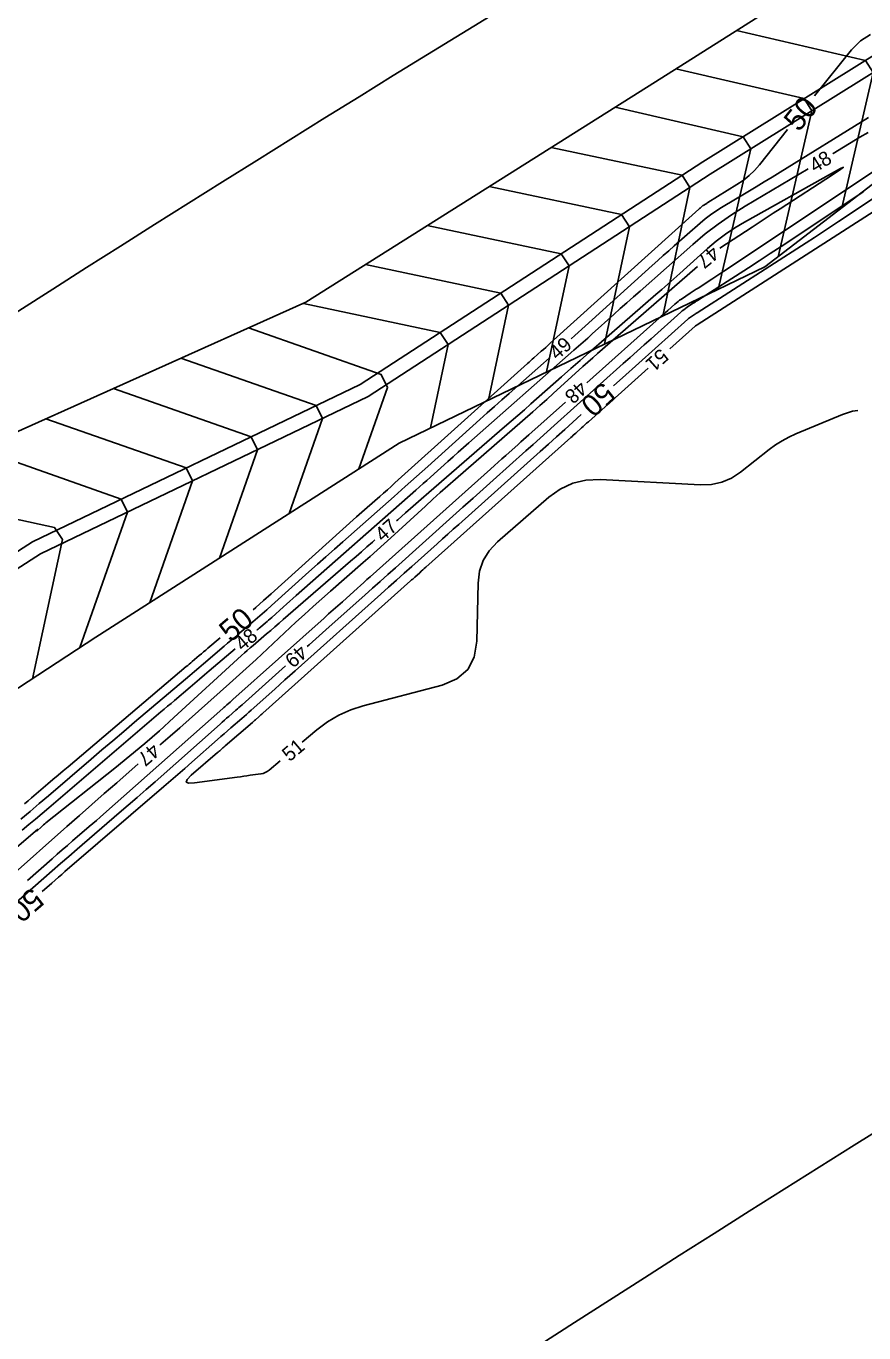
# Model space of a CAD drawing. Extents: x 2384780 to 2405861, y 547869 to 573706.
# Drawn here: x 2392685.5 to 2392801.8, y 553648.5 to 553830.1 of the extents above; entities that cross this region are included whole.
import ezdxf

# ---------------------------------------------------------------- set-up
doc = ezdxf.new("R2010")
doc.units = 0
for name, color, linetype in [('Old_Level_5', 7, 'Continuous'), ('Old_Level_60', 7, 'Continuous'), ('Old_Level_61', 7, 'Continuous'), ('Old_Level_63', 7, 'Continuous'), ('Sheet Plan CELL', 7, 'Continuous')]:
    doc.layers.add(name, color=color, linetype=linetype)

msp = doc.modelspace()

# ---------------------------------------------------------------- linework, layer by layer
at = {"layer": 'Old_Level_5'}
msp.add_arc((2394828.31077, 550434.91596), 3822, 118.42377222, 123.93929722, dxfattribs=at)
at = {"layer": 'Old_Level_60'}
for points in [[(2392802.48475, 553817.3955), (2392790.23975, 553809.82325), (2392789.12175, 553809.13525), (2392788.001, 553808.4515), (2392786.8775, 553807.7725), (2392785.75125, 553807.098), (2392782.0675, 553804.90225), (2392781.29075, 553804.4145), (2392780.539, 553803.89225), (2392779.8125, 553803.33575), (2392779.111, 553802.745), (2392775.52025, 553799.576), (2392774.75175, 553798.89575), (2392773.98525, 553798.2135), (2392773.22075, 553797.529), (2392772.458, 553796.8425), (2392763.14475, 553788.43475), (2392761.701, 553787.13525), (2392761.1815, 553786.6705)], [(2392802.436, 553815.3085), (2392801.27975, 553814.675), (2392797.57975, 553812.387), (2392797.51625, 553812.348)], [(2392794.0955, 553810.27475), (2392785.356, 553805.065), (2392783.45025, 553803.86875), (2392781.60625, 553802.58775), (2392779.82375, 553801.22275), (2392778.10275, 553799.773), (2392770.761, 553793.2935), (2392769.84275, 553792.48075), (2392768.927, 553791.6655), (2392768.01325, 553790.84775), (2392767.102, 553790.0275), (2392764.129, 553787.3435), (2392763.491, 553786.76925), (2392762.8515, 553786.197), (2392762.21, 553785.6265), (2392761.567, 553785.058), (2392746.98375, 553772.20225), (2392746.24925, 553771.553), (2392745.51675, 553770.90175), (2392744.78575, 553770.24825), (2392744.05675, 553769.593), (2392741.67825, 553767.449), (2392741.16775, 553766.99025), (2392740.656, 553766.533), (2392740.143, 553766.07725), (2392739.62875, 553765.623), (2392722.99925, 553750.98), (2392722.556, 553750.5885), (2392722.114, 553750.196), (2392721.67275, 553749.80225), (2392721.23275, 553749.4075), (2392719.60525, 553747.9425), (2392719.393, 553747.75275), (2392719.17925, 553747.56475), (2392718.96425, 553747.3785), (2392718.74775, 553747.1935), (2392718.03825, 553746.59275), (2392717.88625, 553746.46375), (2392717.7345, 553746.33475), (2392717.58275, 553746.2055), (2392717.57375, 553746.19775)], [(2392781.85, 553799.24825), (2392786.31325, 553802.17875), (2392787.2885, 553802.818), (2392788.26475, 553803.456), (2392789.24175, 553804.09225), (2392790.21975, 553804.72725), (2392797.4895, 553809.4395), (2392798.65, 553810.20975), (2392799.016, 553810.50075), (2392798.58775, 553810.31275), (2392797.365, 553809.64575), (2392785.275, 553802.8785), (2392783.9165, 553802.068), (2392782.6095, 553801.186), (2392781.3535, 553800.23225), (2392780.149, 553799.20675), (2392776.298, 553795.74025), (2392775.471, 553794.99925), (2392774.6405, 553794.2625), (2392773.8065, 553793.52975), (2392772.96875, 553792.801), (2392765.03825, 553785.93525), (2392763.731, 553784.79975), (2392762.42725, 553783.66025), (2392761.127, 553782.51675), (2392759.83025, 553781.369), (2392755.6005, 553777.61325), (2392754.69275, 553776.81), (2392753.78275, 553776.00925), (2392752.8705, 553775.21125), (2392751.9555, 553774.416), (2392741.4385, 553765.301), (2392740.3535, 553764.3585), (2392739.27075, 553763.41375), (2392738.19, 553762.46625), (2392737.1115, 553761.51675), (2392736.93925, 553761.36475)], [(2392763.36875, 553780.5345), (2392773.3985, 553789.51475), (2392773.70125, 553789.786), (2392774.00425, 553790.057), (2392774.307, 553790.32825), (2392774.61, 553790.5995), (2392775.59925, 553791.4855), (2392775.8145, 553791.67125), (2392776.03575, 553791.84925), (2392776.26325, 553792.019), (2392776.49675, 553792.181), (2392777.7415, 553793.01125), (2392778.00875, 553793.18875), (2392778.2765, 553793.36475), (2392778.54525, 553793.53975), (2392778.8145, 553793.71375), (2392780.74975, 553794.9565), (2392781.164, 553795.22375), (2392781.577, 553795.49275), (2392781.98875, 553795.7635), (2392782.3995, 553796.036), (2392803.18575, 553809.8895)], [(2392724.52275, 553743.886), (2392724.79125, 553744.1265), (2392726.18775, 553745.377), (2392727.58425, 553746.62775), (2392732.5345, 553751.06075), (2392733.59525, 553752.0105), (2392734.656, 553752.9605), (2392735.71675, 553753.91025), (2392736.7775, 553754.86025), (2392744.77475, 553762.0205), (2392746.1705, 553763.27025), (2392747.56625, 553764.52), (2392748.96225, 553765.77), (2392750.358, 553767.02), (2392754.91725, 553771.103), (2392755.89425, 553771.978), (2392756.8715, 553772.85275), (2392757.8485, 553773.72775), (2392758.8255, 553774.6025), (2392768.4325, 553783.20425), (2392769.401, 553784.07125), (2392770.3695, 553784.9385), (2392771.338, 553785.80575), (2392772.3065, 553786.67325), (2392776.405, 553790.3435), (2392776.6185, 553790.528), (2392776.8385, 553790.70475), (2392777.0645, 553790.8735), (2392777.2965, 553791.03425), (2392778.06475, 553791.54675), (2392778.22975, 553791.65625), (2392778.395, 553791.765), (2392778.56075, 553791.873), (2392778.727, 553791.98025), (2392785.80525, 553796.52625), (2392787.31975, 553797.5035), (2392788.83025, 553798.48725), (2392790.3365, 553799.4775), (2392791.83875, 553800.474), (2392801.73375, 553807.06875)], [(2392803.282, 553804.3965), (2392778.693, 553788.604), (2392778.6625, 553788.5845), (2392778.63225, 553788.56475), (2392778.602, 553788.545), (2392778.572, 553788.525), (2392778.47375, 553788.4595), (2392778.453, 553788.445), (2392778.43275, 553788.43), (2392778.41325, 553788.41425), (2392778.394, 553788.39775), (2392774.88925, 553785.25875)], [(2392704.08525, 553730.21675), (2392704.2055, 553730.32125), (2392705.5175, 553731.46575), (2392706.8265, 553732.61375), (2392708.13225, 553733.76525), (2392709.43525, 553734.92025), (2392713.76475, 553738.7685), (2392714.69, 553739.596), (2392715.6105, 553740.4285), (2392716.526, 553741.2665), (2392717.43675, 553742.11), (2392722.97425, 553747.2685), (2392724.16525, 553748.36925), (2392725.36475, 553749.4605), (2392726.5725, 553750.54225), (2392727.789, 553751.61475), (2392732.3195, 553755.57775), (2392733.28775, 553756.43), (2392734.25075, 553757.288), (2392735.2085, 553758.15175), (2392736.16075, 553759.0215), (2392740.95525, 553763.42675), (2392741.9855, 553764.3675), (2392743.02175, 553765.3015), (2392744.06375, 553766.229), (2392745.112, 553767.14975), (2392755.859, 553776.53125), (2392756.8295, 553777.3825), (2392757.79575, 553778.2385), (2392758.75775, 553779.0995), (2392759.7155, 553779.965), (2392762.8375, 553782.80025), (2392763.508, 553783.406), (2392764.1815, 553784.0085), (2392764.85825, 553784.6075), (2392765.53775, 553785.203), (2392778.75425, 553796.72475)], [(2392758.1935, 553784.011), (2392757.34675, 553783.2625), (2392752.587, 553779.0665), (2392751.56825, 553778.166), (2392750.552, 553777.2625), (2392749.53825, 553776.35625), (2392748.527, 553775.4475), (2392741.27425, 553768.9095), (2392739.718, 553767.511), (2392738.15775, 553766.11675), (2392736.59325, 553764.72725), (2392735.025, 553763.342), (2392729.4925, 553758.4705), (2392728.30825, 553757.42475), (2392727.127, 553756.376), (2392725.9485, 553755.32425), (2392724.773, 553754.269), (2392719.5715, 553749.587), (2392718.932, 553749.016), (2392718.2885, 553748.44975), (2392717.64075, 553747.88825), (2392716.9885, 553747.33175), (2392714.8515, 553745.5215), (2392714.39375, 553745.13325), (2392713.9365, 553744.74475), (2392713.47975, 553744.3555), (2392713.02325, 553743.96575), (2392710.1235, 553741.48625), (2392709.502, 553740.9555), (2392708.87975, 553740.42525), (2392708.25675, 553739.89575), (2392707.63325, 553739.367), (2392700.568, 553733.382), (2392699.05475, 553732.09875), (2392697.54275, 553730.814), (2392696.03225, 553729.52775), (2392694.52275, 553728.23975), (2392688.5895, 553723.171), (2392687.3175, 553722.0855), (2392686.04425, 553721.00125), (2392684.77, 553719.9185)], [(2392771.90925, 553782.59025), (2392763.58525, 553775.136), (2392763.34275, 553774.91875), (2392763.10025, 553774.7015), (2392762.85775, 553774.48425), (2392762.615, 553774.26725), (2392761.82275, 553773.55775), (2392761.653, 553773.40575), (2392761.48325, 553773.25375), (2392761.3135, 553773.10175), (2392761.1435, 553772.9495), (2392741.0095, 553754.91875), (2392740.79875, 553754.73025), (2392740.588, 553754.5415), (2392740.3775, 553754.353), (2392740.16675, 553754.16425), (2392739.47875, 553753.54825), (2392739.33125, 553753.41625), (2392739.18375, 553753.284), (2392739.03625, 553753.152), (2392738.889, 553753.02), (2392718.37075, 553734.64525), (2392718.2285, 553734.51775), (2392718.08625, 553734.3905), (2392717.944, 553734.263), (2392717.80175, 553734.13575), (2392717.337, 553733.71975), (2392717.23725, 553733.63075), (2392717.137, 553733.54225), (2392717.0365, 553733.45425), (2392716.9355, 553733.36675), (2392713.1645, 553730.115), (2392713.0565, 553730.0215), (2392712.9485, 553729.9275), (2392712.841, 553729.833), (2392712.734, 553729.7385), (2392712.38425, 553729.42825), (2392712.30925, 553729.362), (2392712.234, 553729.296), (2392712.15825, 553729.23025), (2392712.0825, 553729.165), (2392708.414, 553726.01325), (2392707.8545, 553725.44), (2392707.748, 553725.07075), (2392708.095, 553724.906), (2392708.895, 553724.94525), (2392714.8045, 553725.75925), (2392715.26025, 553725.822), (2392715.71575, 553725.88475), (2392716.1715, 553725.9475), (2392716.627, 553726.01025), (2392718.1155, 553726.21525), (2392718.4255, 553726.2795), (2392718.717, 553726.385), (2392718.99025, 553726.5315), (2392719.24525, 553726.71875), (2392720.78975, 553728.0245)], [(2392685.69375, 553711.38), (2392689.11175, 553714.413), (2392689.81675, 553715.036), (2392690.524, 553715.65625), (2392691.234, 553716.2735), (2392691.94625, 553716.888), (2392694.27725, 553718.8905), (2392694.77575, 553719.3205), (2392695.27275, 553719.7525), (2392695.768, 553720.1865), (2392696.2615, 553720.6225), (2392712.79875, 553735.2885), (2392712.939, 553735.4125), (2392713.07975, 553735.536), (2392713.22075, 553735.659), (2392713.3625, 553735.7815), (2392713.8255, 553736.181), (2392713.92475, 553736.26675), (2392714.02325, 553736.353), (2392714.1215, 553736.43975), (2392714.2195, 553736.527), (2392726.8695, 553747.85325), (2392727.50675, 553748.424), (2392728.144, 553748.9945), (2392728.78125, 553749.56525), (2392729.41825, 553750.13575), (2392731.49975, 553751.99975), (2392731.946, 553752.39925), (2392732.392, 553752.79875), (2392732.838, 553753.198), (2392733.284, 553753.5975), (2392750.0025, 553768.5665), (2392750.529, 553769.038), (2392751.0555, 553769.50925), (2392751.582, 553769.98075), (2392752.1085, 553770.45225), (2392753.82825, 553771.9925), (2392754.197, 553772.3225), (2392754.5655, 553772.6525), (2392754.934, 553772.9825), (2392755.3025, 553773.3125), (2392760.38875, 553777.8665)], [(2392723.8445, 553730.607), (2392725.8825, 553732.33025), (2392727.35225, 553733.4415), (2392728.91675, 553734.37025), (2392730.576, 553735.11675), (2392732.33, 553735.68075), (2392743.277, 553738.554), (2392745.33675, 553739.396), (2392746.82375, 553740.69), (2392747.73825, 553742.43625), (2392748.08, 553744.63475), (2392748.2655, 553752.70225), (2392748.46325, 553754.35675), (2392748.9775, 553755.86275), (2392749.808, 553757.22), (2392750.955, 553758.42875), (2392758.09675, 553764.637), (2392759.689, 553765.78825), (2392761.405, 553766.581), (2392763.2445, 553767.01575), (2392765.20775, 553767.092), (2392779.17425, 553766.38275), (2392780.68375, 553766.434), (2392782.11075, 553766.745), (2392783.455, 553767.31575), (2392784.7165, 553768.1465), (2392788.7025, 553771.2845), (2392789.57525, 553771.92475), (2392790.48575, 553772.501), (2392791.434, 553773.01275), (2392792.4195, 553773.4605), (2392798.871, 553776.12975), (2392800.26325, 553776.59075), (2392801.024, 553776.71925)], [(2392733.94025, 553758.718), (2392733.5915, 553758.41025), (2392732.8365, 553757.7455), (2392732.08025, 553757.08225), (2392731.32225, 553756.42075), (2392730.563, 553755.761), (2392721.1945, 553747.6365), (2392720.622, 553747.141), (2392720.04875, 553746.6465), (2392719.4745, 553746.15325), (2392718.8995, 553745.66075), (2392717.01925, 553744.054), (2392716.618, 553743.70775), (2392716.2195, 553743.35825), (2392715.82425, 553743.0055), (2392715.43225, 553742.649), (2392706.0225, 553734.022), (2392704.014, 553732.2125), (2392701.9745, 553730.439), (2392699.9045, 553728.7015), (2392697.8035, 553727), (2392688.245, 553719.3965), (2392688.08775, 553719.26875), (2392687.93325, 553719.13725), (2392687.7815, 553719.00275), (2392687.6325, 553718.865), (2392687.021, 553718.28625), (2392686.99125, 553718.26025), (2392686.97775, 553718.2545), (2392686.981, 553718.26875), (2392687.00075, 553718.303), (2392687.092, 553718.44825), (2392687.10575, 553718.4725), (2392687.1075, 553718.483), (2392687.09725, 553718.47975), (2392687.07525, 553718.46275), (2392665.36675, 553699.9315)], [(2392714.5335, 553743.5985), (2392710.929, 553740.5165), (2392710.26425, 553739.949), (2392709.599, 553739.382), (2392708.933, 553738.81575), (2392708.26625, 553738.2505), (2392706.0875, 553736.40475), (2392705.62075, 553736.00925), (2392705.1545, 553735.613), (2392704.68875, 553735.21625), (2392704.22325, 553734.819), (2392688.63775, 553721.505), (2392687.71925, 553720.72125), (2392686.80025, 553719.9385), (2392685.88025, 553719.15675), (2392684.9595, 553718.37575)], [(2392682.6115, 553706.9785), (2392687.95725, 553711.722), (2392689.10475, 553712.73625), (2392690.25625, 553713.74575), (2392691.412, 553714.75075), (2392692.5715, 553715.751), (2392698.42175, 553720.777), (2392699.67325, 553721.8565), (2392700.9205, 553722.94075), (2392702.16325, 553724.03), (2392703.402, 553725.12425), (2392712.4345, 553733.13475), (2392712.73525, 553733.4005), (2392713.037, 553733.66525), (2392713.33975, 553733.929), (2392713.64325, 553734.19175), (2392714.6365, 553735.04825), (2392714.84875, 553735.23225), (2392715.06025, 553735.41725), (2392715.271, 553735.60325), (2392715.48075, 553735.79), (2392721.54275, 553741.21775)], [(2392683.15875, 553711.7545), (2392691.17, 553718.90425), (2392692.88925, 553720.4335), (2392694.613, 553721.95725), (2392696.34175, 553723.47575), (2392698.07525, 553724.9885), (2392701.0675, 553727.5915)]]:
    msp.add_lwpolyline(points, dxfattribs=at)
at = {"layer": 'Old_Level_61'}
for points in [[(2392802.78875, 553828.9235), (2392801.382, 553828.07), (2392800.1465, 553826.8285), (2392795.00425, 553820.4075)], [(2392791.25375, 553815.72425), (2392787.34325, 553810.84125), (2392786.65175, 553810.049), (2392785.90075, 553809.324), (2392785.09, 553808.66625), (2392784.21975, 553808.076), (2392780.17475, 553805.57475), (2392780.09675, 553805.52675), (2392780.01875, 553805.479), (2392779.94025, 553805.4315), (2392779.86175, 553805.3845), (2392779.60475, 553805.23125), (2392779.5505, 553805.19725), (2392779.498, 553805.16075), (2392779.4475, 553805.122), (2392779.3985, 553805.08075), (2392779.148, 553804.85975), (2392779.09425, 553804.81225), (2392779.04075, 553804.76475), (2392778.9875, 553804.717), (2392778.93425, 553804.669), (2392758.28675, 553786.029), (2392757.97675, 553785.75), (2392757.66575, 553785.47175), (2392757.354, 553785.1945), (2392757.0415, 553784.918), (2392756.019, 553784.01675), (2392755.80025, 553783.8235), (2392755.582, 553783.6295), (2392755.36425, 553783.43475), (2392755.147, 553783.2395), (2392736.72425, 553766.63325), (2392736.19775, 553766.16), (2392735.67, 553765.6885), (2392735.14075, 553765.21825), (2392734.61025, 553764.74975), (2392732.87475, 553763.2215), (2392732.50325, 553762.8935), (2392732.13275, 553762.5645), (2392731.763, 553762.2345), (2392731.39425, 553761.9035), (2392719.53775, 553751.23175), (2392718.47125, 553750.279), (2392717.39775, 553749.3345), (2392717.021, 553749.008)], [(2392767.07175, 553780.12175), (2392767.52825, 553780.5305), (2392768.32175, 553781.24125), (2392777.3915, 553789.36325), (2392777.512, 553789.4675), (2392777.636, 553789.567), (2392777.76325, 553789.66225), (2392777.89425, 553789.753), (2392778.3275, 553790.04175), (2392778.4205, 553790.1035), (2392778.51375, 553790.165), (2392778.607, 553790.22575), (2392778.701, 553790.28625), (2392793.839, 553800.009), (2392794.967, 553800.73675), (2392796.092, 553801.46925), (2392797.21375, 553802.20675), (2392798.33225, 553802.94875), (2392803.43375, 553806.34875)], [(2392687.721, 553709.846), (2392689.07475, 553711.04725), (2392689.52675, 553711.44675), (2392689.9805, 553711.8445), (2392690.43575, 553712.2405), (2392690.89275, 553712.6345), (2392704.632, 553724.43825), (2392705.60525, 553725.27775), (2392706.575, 553726.12075), (2392707.5415, 553726.96775), (2392708.50475, 553727.8185), (2392712.07025, 553730.98075), (2392712.53175, 553731.3885), (2392712.9945, 553731.7945), (2392713.4585, 553732.199), (2392713.924, 553732.602), (2392715.44725, 553733.9155), (2392715.773, 553734.1975), (2392716.09725, 553734.48125), (2392716.42025, 553734.7665), (2392716.742, 553735.05325), (2392720.02975, 553737.997), (2392720.73425, 553738.62775), (2392721.43875, 553739.2585), (2392722.14325, 553739.88925), (2392722.84775, 553740.52025), (2392734.77275, 553751.1995), (2392735.84625, 553752.161), (2392736.92, 553753.12225), (2392737.9935, 553754.0835), (2392739.067, 553755.04475), (2392742.57425, 553758.185), (2392743.32575, 553758.858), (2392744.07725, 553759.53075), (2392744.82875, 553760.20375), (2392745.58025, 553760.87675), (2392756.91025, 553771.023), (2392758.04375, 553772.03825), (2392759.17725, 553773.05325), (2392760.311, 553774.06825), (2392761.4445, 553775.08325), (2392762.60175, 553776.1195)], [(2392712.453, 553745.118), (2392710.73225, 553743.66025), (2392710.43475, 553743.40825), (2392710.13775, 553743.15575), (2392709.841, 553742.90275), (2392709.5445, 553742.6495), (2392708.57625, 553741.82175), (2392708.36875, 553741.6445), (2392708.161, 553741.4675), (2392707.953, 553741.29075), (2392707.745, 553741.11425), (2392691.322, 553727.2025), (2392690.6245, 553726.61125), (2392689.92775, 553726.019), (2392689.2315, 553725.42625), (2392688.536, 553724.8325), (2392686.26475, 553722.8925), (2392685.77775, 553722.477), (2392685.2905, 553722.062)]]:
    msp.add_lwpolyline(points, dxfattribs=at)
at = {"layer": 'Old_Level_63'}
msp.add_arc((2394828.31077, 550434.91596), 3982, 118.79726944, 123.93929722, dxfattribs=at)
at = {"layer": 'Sheet Plan CELL'}
for points in [[(2393008.398, 553927.17025), (2392961.427, 553902.4275), (2392917.51975, 553878.505), (2392871.181, 553852.58075), (2392828.0225, 553827.3345), (2392788.076, 553796.64125), (2392737.2995, 553772.17825), (2392695.18775, 553745.21125), (2392653.36, 553717.816), (2392609.89525, 553687.7595), (2392569.78325, 553657.869), (2392527.365, 553625.7965), (2392487.79375, 553595.2155), (2392448.41025, 553564.38), (2392409.161, 553533.36375)], [(2392399.88375, 553545.903), (2392439.06575, 553577.01), (2392478.7045, 553607.50025), (2392518.175, 553638.21775), (2392560.9795, 553670.484), (2392601.23525, 553700.1685), (2392644.36625, 553731.39125), (2392686.40225, 553758.4725), (2392731.9095, 553780.314), (2392779.46625, 553811.242), (2392821.895, 553837.72625), (2392864.53775, 553863.847), (2392910.385, 553891.363), (2392954.08625, 553915.6555)], [(2392401.07325, 553544.29525), (2392440.25525, 553575.40225), (2392479.894, 553605.8925), (2392519.36475, 553636.60975), (2392562.12425, 553668.84375), (2392602.38, 553698.52825), (2392645.471, 553729.72375), (2392687.507, 553756.805), (2392733.0145, 553778.646), (2392780.48225, 553809.51925), (2392822.91075, 553836.0035), (2392865.55375, 553862.124), (2392911.35525, 553889.61425), (2392955.05675, 553913.9065)], [(2392391.61975, 553557.07225), (2392430.4875, 553588.60425), (2392470.201, 553618.9935), (2392510.01325, 553649.249), (2392553.45175, 553681.27075), (2392592.80775, 553712.2445), (2392635.855, 553744.2385), (2392678.09775, 553771.00725), (2392724.3275, 553791.7585), (2392772.89875, 553822.38), (2392815.1775, 553849.11825), (2392857.30175, 553876.11875), (2392903.20675, 553904.299)], [(2392784.13775, 553829.48775), (2392802.055, 553825.342), (2392802.055, 553825.342), (2392802.055, 553825.342), (2392803.117, 553823.64075), (2392798.7715, 553804.85925)], [(2392775.72225, 553824.1655), (2392793.559, 553820.03875), (2392793.559, 553820.03875), (2392793.559, 553820.03875), (2392794.621, 553818.3375), (2392789.931, 553798.0665)], [(2392767.29425, 553818.84675), (2392785.06275, 553814.7355), (2392785.06275, 553814.7355), (2392785.06275, 553814.7355), (2392786.12475, 553813.034), (2392781.6115, 553793.52675)], [(2392758.3945, 553813.236), (2392776.60075, 553809.3785), (2392776.60075, 553809.3785), (2392776.60075, 553809.3785), (2392777.69425, 553807.69725), (2392773.9055, 553789.81425)], [(2392749.80025, 553807.8175), (2392768.20475, 553803.91825), (2392768.20475, 553803.91825), (2392768.20475, 553803.91825), (2392769.29825, 553802.237), (2392765.84325, 553785.93)], [(2392741.20575, 553802.39925), (2392759.80875, 553798.458), (2392759.80875, 553798.458), (2392759.80875, 553798.458), (2392760.902, 553796.7765), (2392757.781, 553782.04575)], [(2392732.6115, 553796.98125), (2392751.4125, 553792.9975), (2392751.4125, 553792.9975), (2392751.4125, 553792.9975), (2392752.506, 553791.31625), (2392749.719, 553778.16175)], [(2392724.01675, 553791.56275), (2392743.0165, 553787.53725), (2392743.0165, 553787.53725), (2392743.0165, 553787.53725), (2392744.10975, 553785.856), (2392741.6565, 553774.2775)], [(2392716.384, 553788.193), (2392734.82475, 553781.71325), (2392734.82475, 553781.71325), (2392734.82475, 553781.71325), (2392735.6925, 553779.905), (2392731.7225, 553768.607)], [(2392707.0045, 553783.98275), (2392725.7955, 553777.3795), (2392725.7955, 553777.3795), (2392725.7955, 553777.3795), (2392726.66325, 553775.5715), (2392722.03625, 553762.40425)], [(2392697.62425, 553779.77225), (2392716.766, 553773.04575), (2392716.766, 553773.04575), (2392716.766, 553773.04575), (2392717.634, 553771.23775), (2392712.35025, 553756.2015)], [(2392688.244, 553775.5615), (2392707.73675, 553768.71225), (2392707.73675, 553768.71225), (2392707.73675, 553768.71225), (2392708.6045, 553766.904), (2392702.6645, 553749.999)], [(2392678.864, 553771.35125), (2392698.7075, 553764.3785), (2392698.7075, 553764.3785), (2392698.7075, 553764.3785), (2392699.57525, 553762.57025), (2392692.96375, 553743.75475)], [(2392668.55825, 553764.96225), (2392689.457, 553760.4405), (2392689.457, 553760.4405), (2392689.457, 553760.4405), (2392690.543, 553758.7545), (2392686.362, 553739.43075)]]:
    msp.add_lwpolyline(points, dxfattribs=at)

# ---------------------------------------------------------------- texts
at = {"layer": 'Old_Level_60'}
for s, rotation, p in [('48', 31.2188028, (2392795.0425, 553809.66975)), ('47', 219.1845361, (2392780.74075, 553799.7195)), ('49', 41.6698139, (2392759.24875, 553783.6075)), ('51', 221.8454139, (2392773.57675, 553785.426)), ('48', 221.8396889, (2392762.332, 553780.9485)), ('47', 41.4288083, (2392735.027, 553758.34325)), ('48', 40.5295139, (2392715.5605, 553743.161)), ('49', 221.8411917, (2392723.4685, 553744.28425)), ('47', 221.0213333, (2392703.00125, 553730.59925)), ('51', 40.2123778, (2392722.097, 553727.82025))]:
    msp.add_text(s, height=2, rotation=rotation, dxfattribs=at).set_placement(p)
at = {"layer": 'Old_Level_61'}
for rotation, p in [(51.3101083, (2392792.82325, 553815.2845)), (221.8404667, (2392765.596, 553780.81375)), (40.4178222, (2392713.91625, 553744.3835)), (221.0048306, (2392686.268, 553710.545))]:
    msp.add_text('50', height=3, rotation=rotation, dxfattribs=at).set_placement(p)

doc.saveas('drawing.dxf')
